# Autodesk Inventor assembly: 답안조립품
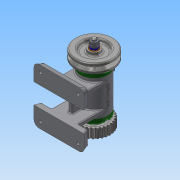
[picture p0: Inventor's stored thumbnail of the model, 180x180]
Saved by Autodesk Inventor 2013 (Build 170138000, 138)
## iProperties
Created: 2016-07
Part Number: 답안조립품
Document SubType Name: Assembly
Designer: Administrator
Author: Administrator
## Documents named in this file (16)
- C:\Users\Administrator\Desktop\460708V1007\답안조립품.iam
- C:\Users\Administrator\Desktop\460708V1007\본체.ipt
- C:\Users\Administrator\Desktop\460708V1007\V벨트풀리.ipt
- C:\Users\Administrator\Desktop\460708V1007\너트 M 8.ipt
- C:\Users\Administrator\Desktop\460708V1007\니플 M 6 x 0.75.ipt
- C:\Users\Administrator\Desktop\460708V1007\베어링 15 x 32 x 9.ipt
- C:\Users\Administrator\Desktop\460708V1007\볼트 M 6 x 8.ipt
- C:\Users\Administrator\Desktop\460708V1007\볼트 M4 x 12.ipt
- C:\Users\Administrator\Desktop\460708V1007\스퍼기어.ipt
- C:\Users\Administrator\Desktop\460708V1007\스프링와셔 8.ipt
- C:\Users\Administrator\Desktop\460708V1007\오일 실 15 25 7.ipt
- C:\Users\Administrator\Desktop\460708V1007\와셔 6x11.5.ipt
- C:\Users\Administrator\Desktop\460708V1007\와셔 8x17.ipt
- C:\Users\Administrator\Desktop\460708V1007\축.ipt
- C:\Users\Administrator\Desktop\460708V1007\커버.ipt
- C:\Users\Administrator\Desktop\460708V1007\키 3 x 3 x 12.ipt
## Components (11 placed, 3 different names)
1. V벨트풀리:1
2. KS B 2023 6002 - 15 x 32 x 9:1
3. KS B 2023 6002 - 15 x 32 x 9:2
4. ISO 4762 M4 x 12:1
5. ISO 4762 M4 x 12:3
6. ISO 4762 M4 x 12:4
7. ISO 4762 M4 x 12:5
8. ISO 4762 M4 x 12:2
9. ISO 4762 M4 x 12:6
10. ISO 4762 M4 x 12:7
11. ISO 4762 M4 x 12:8
